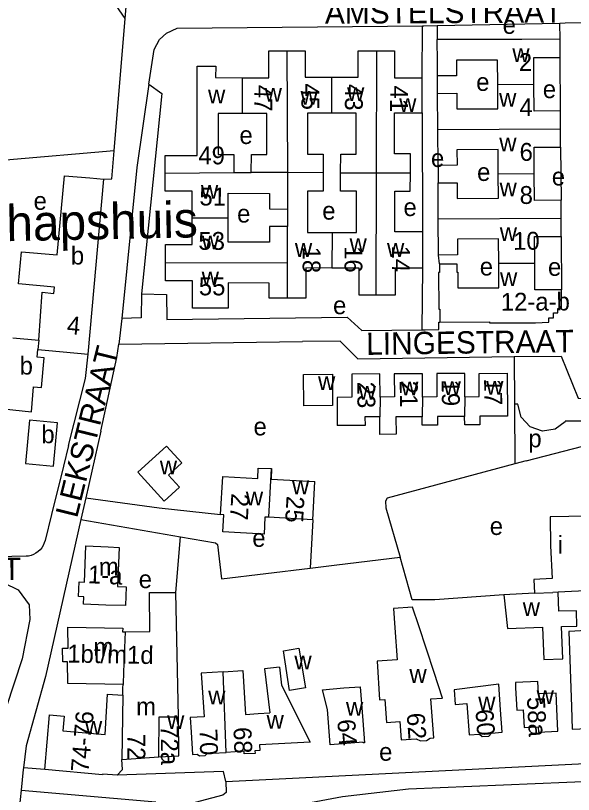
# Model space of a CAD drawing. Extents: x 156721 to 158827, y 386657 to 388950.
# Drawn here: x 157877.1 to 158001.9, y 387819.8 to 387994 of the extents above; entities that cross this region are included whole.
import ezdxf

# ---------------------------------------------------------------- set-up
doc = ezdxf.new("R2010")
doc.units = 0
for name, color, linetype in [('BLT_Basislijn', 7, 'Continuous'), ('BLT_Bebouwing', 7, 'Continuous'), ('BLT_Bebouwing_beschrifting', 7, 'Continuous'), ('BLT_Centroide', 7, 'Continuous'), ('BLT_Huisnummer', 7, 'Continuous'), ('BLT_Huisnummer_ tussenligend', 7, 'Continuous'), ('BLT_Huisnummer_reeks', 7, 'Continuous'), ('BLT_Onderverdeling_panden', 7, 'Continuous'), ('BLT_Straatnaam', 7, 'Continuous')]:
    doc.layers.add(name, color=color, linetype=linetype)

msp = doc.modelspace()

# ---------------------------------------------------------------- linework, layer by layer
at = {"layer": 'BLT_Basislijn'}
for p, q in [((157899.13, 387963.78), (157901.62, 387993.36)), ((157968.02, 387980.09), (157968.06, 387991.73)), ((157971.35, 387991.78), (157998.82, 387992.34)), ((157971.35, 387991.78), (157971.4, 387988.63)), ((157998.87, 387988.71), (157998.82, 387992.34)), ((157998.96, 387972.69), (157998.9, 387984.64)), ((157971.48, 387976.61), (157971.45, 387980.53)), ((157968, 387972.25), (157968.1, 387945.64)), ((157999, 387964.6), (157999.09, 387952.71)), ((157971.57, 387960.51), (157971.57, 387956.59)), ((157999.14, 387944.62), (157999.19, 387932.68)), ((157971.9, 387938.5), (157971.66, 387940.45)), ((157968.08, 387937.52), (157967.93, 387923.75)), ((157900.86, 387926.26), (157900.15, 387920.51)), ((157900.15, 387920.51), (157941.29, 387921.13)), ((157953.6, 387917.26), (157988.63, 387917.77)), ((157988.63, 387917.77), (157988.69, 387907.1)), ((157988.69, 387907.1), (157988.77, 387893.76)), ((158000.11, 387903.37), (158026.76, 387903.49)), ((157896.14, 387901.07), (157892.77, 387886.15)), ((157991.27, 387894.43), (158008.88, 387899.04)), ((157888.94, 387897.89), (157887.79, 387893.25)), ((157887.79, 387893.25), (157885.11, 387882.45)), ((157892.77, 387886.15), (157891.67, 387881.33)), ((157885.11, 387882.45), (157883.67, 387876.65)), ((157891.67, 387881.33), (157913.95, 387877.46)), ((157943.53, 387881.27), (157943, 387870.43)), ((157912.94, 387865.01), (157913.95, 387877.46)), ((157879.41, 387873.08), (157866.57, 387872.9)), ((157883.61, 387825.37), (157878.83, 387825.77)), ((157924.07, 387822.72), (158010.48, 387827.06)), ((157878.29, 387820.78), (157908.48, 387818.14))]:
    msp.add_line(p, q, dxfattribs=at)
for points in [[(157901.62, 387993.36), (157898.09, 387998.47), (157897.02, 388000.69), (157896.24, 388041.41), (157895.78, 388042.36), (157892.24, 388044.78)], [(157901.62, 387993.36), (157901.91, 387996.85), (157904.01, 387996.92)], [(157906.88, 387978.67), (157908.09, 387986.41), (157909.3, 387988.64), (157910.8, 387990.08), (157913.24, 387991.17), (157968.06, 387991.73)], [(157968.06, 387991.73), (157968.39, 387991.73), (157971.35, 387991.78)], [(157998.82, 387992.34), (157999.99, 387992.36), (158006.77, 387992.45)], [(157906.88, 387978.67), (157904.21, 387960.07), (157900.86, 387926.26)], [(157906.88, 387978.67), (157909.79, 387976.62), (157905.23, 387931.8)], [(157899.13, 387963.78), (157874.87, 387961.65)], [(157896.83, 387957.41), (157898.6, 387957.51), (157899.13, 387963.78)], [(157905.23, 387931.8), (157905.13, 387926.4), (157900.86, 387926.26)], [(157905.23, 387931.8), (157910.84, 387931.63), (157910.93, 387926.07), (157951.27, 387926.55), (157954.56, 387923.56), (157967.93, 387923.75)], [(157971.73, 387923.79), (157971.73, 387925.44), (157971.95, 387925.44)], [(157967.93, 387923.75), (157968.68, 387923.76), (157971.73, 387923.79)], [(157896.14, 387901.07), (157899.73, 387917.52), (157900.15, 387920.51)], [(157953.6, 387917.26), (157949.7, 387921.17), (157941.29, 387921.13)], [(157888.94, 387897.89), (157892.75, 387912.84), (157893.3, 387918.28)], [(157988.63, 387917.77), (157999.1, 387917.81), (158002.93, 387908.43), (158009.43, 387908.41)], [(158000.11, 387903.37), (158000, 387903.14), (157997.74, 387901.5), (157994.97, 387901.07), (157992.16, 387902.04), (157990.14, 387904.22), (157989.43, 387907.11), (157988.69, 387907.1)], [(157988.77, 387893.76), (157960.18, 387886.1), (157959.79, 387885.42)], [(157991.27, 387894.43), (157988.77, 387893.76)], [(157892.77, 387886.15), (157909.16, 387883.95), (157922.94, 387882.41)], [(157959.79, 387885.42), (157959.92, 387883.94), (157963.07, 387872.89)], [(157891.67, 387881.33), (157883.75, 387846.18), (157879.46, 387830.71), (157878.83, 387825.77)], [(157883.67, 387876.65), (157883.5, 387876.07), (157883.26, 387875.52), (157882.95, 387875), (157882.57, 387874.53), (157882.13, 387874.12), (157881.64, 387873.77), (157881.11, 387873.48), (157880.55, 387873.27), (157879.96, 387873.13), (157879.41, 387873.08)], [(157913.95, 387877.46), (157921.83, 387876.09), (157922.24, 387875.71), (157923.13, 387868.05), (157943, 387870.43)], [(157943, 387870.43), (157948.92, 387871.14), (157963.07, 387872.89)], [(157986.29, 387864.45), (157970.85, 387863.35), (157965.79, 387863.37), (157963.07, 387872.89)], [(157841.97, 387866.69), (157874.43, 387867.12), (157877.68, 387865.6), (157880.08, 387862.25), (157880.27, 387858.93), (157878.55, 387850.12), (157874.95, 387839.3), (157872.31, 387828.07)], [(157878.83, 387825.77), (157878.79, 387825.42), (157878.29, 387820.78)], [(157924.07, 387822.72), (157923.55, 387824.93), (157899.81, 387824.11)], [(157926.23, 387812.97), (157939.48, 387817.32), (157950.17, 387819.38), (157964.96, 387821.05), (158050, 387824.67)], [(157924.07, 387822.72), (157924.19, 387820.24), (157923.41, 387819.68), (157908.49, 387815.69)], [(157878.29, 387820.78), (157877.85, 387816.63), (157877.67, 387804.99)]]:
    msp.add_lwpolyline(points, dxfattribs=at)
at = {"layer": 'BLT_Bebouwing'}
for p, q in [((157998.9, 387984.64), (157998.87, 387988.71)), ((157971.52, 387968.56), (157971.48, 387976.61)), ((157998.98, 387968.71), (157998.96, 387972.69)), ((157971.57, 387960.51), (157971.52, 387968.56)), ((157999, 387964.6), (157998.98, 387968.71)), ((157925.92, 387958.95), (157929.8, 387958.94)), ((157893.3, 387918.28), (157896.83, 387957.41)), ((157971.62, 387948.52), (157971.57, 387956.59)), ((157999.11, 387948.67), (157999.09, 387952.71)), ((157937.9, 387950.75), (157937.9, 387946.86)), ((157971.66, 387940.45), (157971.62, 387948.52)), ((157884.48, 387919.08), (157893.3, 387918.28)), ((157941.47, 387913.73), (157947.97, 387913.79)), ((157941.52, 387906.74), (157941.47, 387913.73)), ((157880.17, 387903.5), (157879.27, 387893.84)), ((157910.85, 387897.71), (157904.43, 387891.88)), ((157914.25, 387893.96), (157910.85, 387897.71)), ((157879.27, 387893.84), (157885.54, 387893.26)), ((157911.27, 387891.26), (157914.25, 387893.96)), ((157910.28, 387885.43), (157904.43, 387891.88)), ((157934.33, 387892.69), (157934.21, 387890.36)), ((157911.27, 387891.26), (157913.74, 387888.57)), ((157910.28, 387885.43), (157913.74, 387888.57)), ((157943.53, 387881.27), (157944, 387889.82)), ((157913.55, 387837.21), (157912.94, 387865.01)), ((157993.12, 387864.81), (157986.29, 387864.45)), ((158009.5, 387865.58), (157998.46, 387865.05)), ((157998.56, 387860.82), (157998.46, 387865.05)), ((157936.08, 387848.31), (157936.58, 387844.29)), ((157936.58, 387844.29), (157942.96, 387831.51)), ((157931.33, 387837.89), (157933.98, 387838.04)), ((157900.83, 387827.63), (157909.15, 387828.2))]:
    msp.add_line(p, q, dxfattribs=at)
for points in [[(157998.87, 387988.71), (157990.34, 387988.67), (157971.4, 387988.63)], [(157971.45, 387980.53), (157971.43, 387983.63), (157971.4, 387988.63)], [(157927.77, 387980.12), (157933.71, 387980.1), (157933.72, 387986.16), (157937.77, 387986.15)], [(157937.77, 387986.15), (157941.83, 387986.14), (157941.82, 387980.26), (157947.77, 387980.25)], [(157947.77, 387980.25), (157953.73, 387980.24), (157953.74, 387986.12), (157957.79, 387986.11)], [(157957.79, 387986.11), (157961.84, 387986.11), (157961.82, 387980.11), (157968.02, 387980.09)], [(157993, 387978.66), (157992.97, 387984.61), (157998.9, 387984.64)], [(157910.52, 387958.74), (157910.53, 387962.71), (157917.67, 387962.69), (157917.72, 387982.68), (157921.84, 387982.67), (157921.83, 387980.13), (157927.77, 387980.12)], [(157984.94, 387978.62), (157984.91, 387984.06), (157975.7, 387984.01), (157975.72, 387980.55), (157971.45, 387980.53)], [(157968, 387972.25), (157968.01, 387975.1), (157968.02, 387980.09)], [(157971.48, 387976.61), (157975.75, 387976.64), (157975.77, 387973.13), (157984.97, 387973.18), (157984.94, 387978.62)], [(157998.96, 387972.69), (157993.04, 387972.66), (157993, 387978.66)], [(157927.75, 387972.13), (157922.4, 387972.14), (157922.38, 387962.93), (157925.93, 387962.92), (157925.92, 387958.95)], [(157929.8, 387958.94), (157929.81, 387962.95), (157933.28, 387962.95), (157933.3, 387972.12), (157927.75, 387972.13)], [(157947.75, 387972.2), (157942.38, 387972.21), (157942.36, 387963.02), (157945.89, 387963.01), (157945.88, 387958.87)], [(157949.79, 387958.88), (157949.8, 387963.04), (157953.27, 387963.04), (157953.29, 387972.19), (157947.75, 387972.2)], [(157965.38, 387958.85), (157965.39, 387963.07), (157961.85, 387963.08), (157961.87, 387972.27), (157968, 387972.25)], [(157985.04, 387958.61), (157985.01, 387964.05), (157975.81, 387964.01), (157975.83, 387960.53), (157971.57, 387960.51)], [(157993.08, 387958.66), (157993.05, 387964.56), (157999, 387964.6)], [(157885.63, 387931.88), (157885.78, 387933.31), (157877.75, 387934.03), (157878.4, 387941.21), (157886.4, 387940.48), (157888.01, 387958.2), (157893.65, 387957.69), (157896.83, 387957.41)], [(157916.6, 387948.79), (157916.61, 387954.76), (157910.51, 387954.77), (157910.52, 387958.74)], [(157945.88, 387958.87), (157945.87, 387954.72), (157942.41, 387954.73), (157942.39, 387945.53), (157947.87, 387945.52)], [(157947.87, 387945.52), (157953.34, 387945.5), (157953.36, 387954.72), (157949.78, 387954.73), (157949.79, 387958.88)], [(157968.1, 387945.64), (157961.91, 387945.65), (157961.93, 387954.77), (157965.37, 387954.77), (157965.38, 387958.85)], [(157971.57, 387956.59), (157975.85, 387956.62), (157975.87, 387953.13), (157985.07, 387953.18), (157985.04, 387958.61)], [(157999.09, 387952.71), (157993.12, 387952.68), (157993.08, 387958.66)], [(157924.65, 387948.77), (157924.66, 387954.26), (157933.87, 387954.24), (157933.86, 387950.76), (157937.9, 387950.75)], [(157910.61, 387938.76), (157910.62, 387942.83), (157916.59, 387942.82), (157916.6, 387948.79)], [(157937.9, 387946.86), (157933.91, 387946.87), (157933.9, 387943.35), (157924.63, 387943.37), (157924.65, 387948.77)], [(157999.14, 387944.62), (157999.11, 387948.67)], [(157968.1, 387945.64), (157968.09, 387942.52), (157968.08, 387937.52)], [(157993.21, 387938.65), (157993.18, 387944.59), (157999.14, 387944.62)], [(157985.15, 387938.61), (157985.12, 387944.06), (157975.94, 387944.01), (157975.95, 387940.47), (157971.66, 387940.45)], [(157937.9, 387930.79), (157933.82, 387930.8), (157933.82, 387934.2), (157924.64, 387934.22), (157924.63, 387928.58), (157916.67, 387928.6), (157916.68, 387934.67), (157910.6, 387934.68), (157910.61, 387938.76)], [(157947.85, 387937.56), (157941.99, 387937.57), (157941.98, 387930.78), (157937.9, 387930.79)], [(157957.67, 387931.52), (157953.9, 387931.52), (157953.92, 387937.54), (157947.85, 387937.56)], [(157968.08, 387937.52), (157962, 387937.53), (157961.99, 387931.51), (157957.67, 387931.52)], [(157971.9, 387938.5), (157971.92, 387936.55), (157971.68, 387936.55), (157971.72, 387928.34), (157971.94, 387928.34), (157971.95, 387925.44)], [(157971.9, 387938.5), (157975.75, 387938.52), (157975.76, 387936.65), (157976, 387936.65), (157976.02, 387933.11), (157985.17, 387933.16), (157985.15, 387938.61)], [(157999.19, 387932.68), (157993.24, 387932.65), (157993.21, 387938.65)], [(157882.26, 387921.42), (157883.05, 387932.13), (157885.63, 387931.88)], [(157999.21, 387928.49), (157999.19, 387932.68)], [(157971.95, 387925.44), (157983.11, 387925.5), (157983.11, 387925.28), (157993.34, 387925.33), (157996.34, 387925.44), (157996.33, 387926.45), (157997.4, 387926.45), (157997.39, 387927.5), (157998.35, 387927.51), (157998.34, 387928.47), (157999.21, 387928.49)], [(157876.48, 387921.94), (157882.26, 387921.42)], [(157874.37, 387906.03), (157880.62, 387905.36), (157881.12, 387910.97), (157882.88, 387910.81), (157883.48, 387917.47), (157881.88, 387917.61), (157882.03, 387919.3)], [(157882.03, 387919.3), (157884.48, 387919.08)], [(157947.97, 387913.79), (157948, 387906.78), (157941.52, 387906.74)], [(157958.64, 387908.68), (157958.58, 387913.86), (157952.27, 387913.81), (157952.3, 387908.64), (157948.99, 387908.59), (157949.02, 387902.32)], [(157968.08, 387908.71), (157968.06, 387913.92), (157961.78, 387913.9), (157961.84, 387908.72), (157958.64, 387908.68)], [(157977.6, 387908.77), (157977.57, 387913.96), (157971.27, 387913.94), (157971.29, 387908.72), (157968.08, 387908.71)], [(157977.6, 387908.77), (157980.81, 387908.79), (157980.77, 387913.98), (157987.05, 387914.01), (157987.14, 387904.43), (157980.92, 387904.4), (157980.92, 387902.49), (157977.53, 387902.46), (157977.52, 387904.36)], [(157958.55, 387904.28), (157955.23, 387904.27), (157955.24, 387902.35), (157949.02, 387902.32)], [(157968.04, 387904.29), (157962.15, 387904.25), (157962.18, 387900.39), (157958.56, 387900.35), (157958.55, 387904.28)], [(157977.52, 387904.36), (157971.45, 387904.35), (157971.46, 387902.43), (157968.05, 387902.41), (157968.04, 387904.29)], [(157885.54, 387893.26), (157886.43, 387902.91), (157880.17, 387903.5)], [(157922.94, 387882.41), (157923.41, 387890.93), (157931.24, 387890.5), (157931.37, 387892.82), (157934.21, 387892.7)], [(157934.21, 387892.7), (157934.33, 387892.69)], [(157934.21, 387890.36), (157944, 387889.82)], [(157933.68, 387881.81), (157932.86, 387881.86), (157932.65, 387878.02), (157923.44, 387878.53), (157923.66, 387882.37), (157922.94, 387882.41)], [(157943.53, 387881.27), (157933.68, 387881.81)], [(158009.16, 387882.14), (157996.64, 387881.91), (157996.76, 387875.44), (157997.09, 387868.09)], [(157897.81, 387875.18), (157900.27, 387875.08), (157899.89, 387866.34), (157901.82, 387866.29), (157901.66, 387862.05), (157897.26, 387862.17), (157892.26, 387862.39), (157892.33, 387864.03), (157891.15, 387864.08), (157891.29, 387867.34), (157892.46, 387867.29), (157892.81, 387875.4), (157897.81, 387875.18)], [(157997.09, 387868.09), (157992.97, 387867.93), (157993.12, 387864.81)], [(157901.6, 387856.2), (157907.09, 387856.23), (157907.04, 387864.98), (157912.94, 387865.01)], [(157986.29, 387864.45), (157987.12, 387856.97), (157994.95, 387857.26), (157995.26, 387849.98), (157999.48, 387850.16), (157999.17, 387857.36), (158002.6, 387857.44), (158002.52, 387860.92), (157998.56, 387860.82)], [(157967.26, 387857.51), (157965.88, 387861.7), (157961.6, 387861.39), (157961.93, 387857.12), (157962.41, 387849.92), (157957.97, 387849.65), (157958.49, 387841), (157959.65, 387841.09), (157960.02, 387835.94), (157963.03, 387836.16), (157963.33, 387832.04), (157966.66, 387832.28), (157967.65, 387831.8), (157969.01, 387831.9), (157969.8, 387832.43), (157970.65, 387832.5), (157969.96, 387841.19), (157972.58, 387841.36), (157970.7, 387847.08), (157967.26, 387857.51)], [(157901.14, 387844.43), (157888.73, 387844.66), (157888.71, 387849.47), (157887.62, 387849.47), (157887.6, 387852.56), (157888.81, 387852.56), (157888.79, 387857.26), (157901.03, 387856.98), (157901.01, 387856.19), (157901.6, 387856.2)], [(158010.06, 387847.03), (158005.34, 387846.76), (158004.78, 387856.47), (158000.8, 387856.28)], [(158000.8, 387856.28), (158001.39, 387839.39), (158001.56, 387834.39), (158006.8, 387834.63), (158006.59, 387838.37), (158010.12, 387838.57)], [(157936.99, 387851.94), (157940.44, 387852.51), (157941.9, 387843.66), (157938.38, 387843.05), (157936.99, 387851.94)], [(157923.48, 387847.25), (157918.59, 387846.96), (157919.24, 387837.19), (157916.15, 387837.03), (157916.34, 387833.76), (157916.63, 387828.77), (157917.68, 387828.83), (157918.2, 387828.43), (157919.51, 387828.51), (157919.91, 387828.96), (157921.16, 387829.03), (157924.16, 387829.23)], [(157923.48, 387847.25), (157927.93, 387847.51), (157928.5, 387837.73), (157931.33, 387837.89)], [(157936.08, 387848.31), (157932.77, 387847.9), (157933.98, 387838.04)], [(157998.14, 387838.94), (157997.96, 387842.49), (157994.03, 387842.3), (157993.89, 387845.09), (157988.87, 387844.85), (157988.92, 387843.7), (157989.17, 387838.7), (157990.64, 387838.78), (157990.83, 387834.83), (157993.99, 387834.98), (157994.05, 387833.73), (157998.38, 387833.94), (157998.14, 387838.94)], [(157901.05, 387842.05), (157901.07, 387843.66), (157901.14, 387844.43)], [(157954.73, 387836.36), (157955.13, 387831.38), (157954.81, 387831.35), (157954.8, 387831.49), (157947.47, 387830.9), (157947.07, 387835.89), (157946.83, 387838.8), (157945.72, 387843.24), (157950.52, 387843.63), (157954.12, 387843.92), (157954.73, 387836.36)], [(157985.58, 387838.72), (157985.18, 387844.48), (157975.19, 387843.23), (157975.42, 387839.94), (157978.02, 387840.13), (157978.51, 387833.15), (157980.85, 387833.31), (157981.48, 387832.77), (157982.92, 387832.87), (157983.52, 387833.56), (157985.94, 387833.73), (157985.58, 387838.72)], [(157883.61, 387825.37), (157884.68, 387837.64), (157887.94, 387837.36), (157887.65, 387834.07), (157897.14, 387833.24), (157897.65, 387842.24), (157901.05, 387842.05)], [(157909.15, 387828.2), (157913.59, 387828.49), (157913.55, 387837.21)], [(157931.62, 387830.95), (157931.7, 387829.64), (157930.6, 387829.58), (157930.64, 387829.01), (157928.24, 387828.87), (157928.2, 387829.5), (157924.16, 387829.23)], [(157942.96, 387831.51), (157931.62, 387830.95)], [(157899.81, 387824.11), (157900.98, 387825.39), (157900.83, 387827.63)], [(157899.81, 387824.11), (157896.56, 387824.39), (157896.53, 387824.21), (157883.61, 387825.37)]]:
    msp.add_lwpolyline(points, dxfattribs=at)
at = {"layer": 'BLT_Onderverdeling_panden'}
for p, q in [((157937.77, 387986.15), (157937.88, 387958.9)), ((157957.79, 387986.11), (157957.73, 387958.87)), ((157927.77, 387980.12), (157927.75, 387972.13)), ((157947.77, 387980.25), (157947.75, 387972.2)), ((157984.94, 387978.62), (157993, 387978.66)), ((157971.52, 387968.56), (157998.98, 387968.71)), ((157910.52, 387958.74), (157925.92, 387958.95)), ((157937.88, 387958.9), (157929.8, 387958.94)), ((157937.88, 387958.9), (157937.9, 387950.75)), ((157945.88, 387958.87), (157937.88, 387958.9)), ((157949.79, 387958.88), (157957.73, 387958.87)), ((157957.73, 387958.87), (157957.67, 387931.52)), ((157957.73, 387958.87), (157965.38, 387958.85)), ((157985.04, 387958.61), (157993.08, 387958.66)), ((157916.6, 387948.79), (157924.65, 387948.77)), ((157971.62, 387948.52), (157999.11, 387948.67)), ((157937.9, 387938.7), (157937.9, 387946.86)), ((157947.87, 387945.52), (157947.85, 387937.56)), ((157910.61, 387938.76), (157937.9, 387938.7)), ((157937.9, 387930.79), (157937.9, 387938.7)), ((157985.15, 387938.61), (157993.21, 387938.65)), ((157882.26, 387921.42), (157882.03, 387919.3)), ((157958.64, 387908.68), (157958.55, 387904.28)), ((157968.08, 387908.71), (157968.04, 387904.29)), ((157977.6, 387908.77), (157977.52, 387904.36)), ((157934.21, 387892.7), (157933.68, 387881.81)), ((157993.12, 387864.81), (157997.22, 387865)), ((157998.46, 387865.05), (157997.22, 387865)), ((157901.6, 387856.2), (157901.25, 387847.21)), ((157924.16, 387829.23), (157923.48, 387847.25))]:
    msp.add_line(p, q, dxfattribs=at)
for points in [[(157901.25, 387847.21), (157901.14, 387844.43)], [(157901.05, 387842.05), (157900.83, 387827.63)], [(157909.15, 387828.2), (157909.16, 387837.21), (157913.55, 387837.21)]]:
    msp.add_lwpolyline(points, dxfattribs=at)

# ---------------------------------------------------------------- texts
at = {"layer": 'BLT_Bebouwing_beschrifting'}
msp.add_text('Gemeenschapshuis', height=8, rotation=1.1997, dxfattribs=at).set_placement((157823.37, 387942.46))
at = {"layer": 'BLT_Centroide'}
for s, p in [('e', (157986.02, 387989.94)), ('w', (157988.19, 387983.64)), ('e', (157980.11, 387977.17)), ('w', (157920.12, 387974.37)), ('w', (157932.79, 387974.76)), ('w', (157951.23, 387974.92)), ('e', (157995.01, 387975.56)), ('w', (157940.81, 387974.06)), ('w', (157962.88, 387972.47)), ('w', (157985.23, 387973.62)), ('e', (157927.15, 387965.29)), ('w', (157985.27, 387963.62)), ('e', (157969.99, 387960.15)), ('e', (157980.31, 387957.03)), ('e', (157997.02, 387956.03)), ('w', (157985.34, 387953.61)), ('w', (157918.54, 387953.05)), ('e', (157881.1, 387950.58)), ('e', (157945.67, 387948.38)), ('e', (157963.84, 387949.18)), ('e', (157926.63, 387947.73)), ('w', (157985.38, 387943.61)), ('w', (157918.71, 387941.7)), ('w', (157951.78, 387941.15)), ('b', (157889.44, 387938.34)), ('w', (157939.56, 387940.05)), ('w', (157960.16, 387940.05)), ('e', (157980.91, 387935.89)), ('e', (157996.17, 387935.81)), ('w', (157918.71, 387933.66)), ('w', (157985.44, 387933.52)), ('e', (157948.09, 387927.23)), ('b', (157877.98, 387913.73)), ('w', (157944.73, 387910.25)), ('w', (157953.81, 387908.08)), ('w', (157963.31, 387909.08)), ('w', (157972.81, 387909.14)), ('w', (157982.33, 387909.2)), ('b', (157882.84, 387898.38)), ('e', (157930.3, 387900.12)), ('p', (157991.78, 387897.46)), ('w', (157909.34, 387891.41)), ('w', (157938.89, 387886.97)), ('w', (157928.58, 387884.45)), ('e', (157983.14, 387877.85)), ('e', (157930.02, 387875.21)), ('i', (157998.36, 387873.66)), ('m', (157895.7, 387868.77)), ('e', (157904.62, 387865.97)), ('w', (157990.52, 387859.74)), ('m', (157894.5, 387850.84)), ('w', (157939.44, 387847.78)), ('w', (157965.17, 387844.77)), ('w', (157993.62, 387840.03)), ('w', (157920.16, 387839.97)), ('w', (157980.56, 387838.59)), ('m', (157904.03, 387837.5)), ('w', (157950.98, 387837.42)), ('w', (157892.59, 387833.16)), ('w', (157910.97, 387834.48)), ('w', (157933.22, 387834.52)), ('e', (157958.39, 387827.36))]:
    msp.add_text(s, height=4, dxfattribs=at).set_placement(p)
at = {"layer": 'BLT_Huisnummer'}
for s, rotation, p in [('2', 0.3054, (157989.65, 387981.6)), ('47', 269.8781, (157930.52, 387978.52)), ('41', 269.8738, (157960.87, 387978.38)), ('6', 0.3054, (157989.82, 387961.52)), ('49', 359.8869, (157917.95, 387960.75)), ('18', 270.007, (157941.29, 387942.36)), ('14', 269.8722, (157961.27, 387942.58)), ('55', 359.8777, (157918.06, 387931.45)), ('4', 354.846, (157888.44, 387922.86)), ('23', 270.3327, (157953.51, 387912.13)), ('17', 270.4973, (157981.88, 387912.81)), ('27', 266.8246, (157925.36, 387887.22)), ('25', 266.8246, (157937.71, 387886.65)), ('58a', 272.8081, (157991.46, 387841.57)), ('62', 274.1282, (157964.56, 387837.94)), ('60', 274.0477, (157979.94, 387838.75)), ('64', 274.625, (157949.02, 387836.5)), ('72a', 270.2953, (157909.55, 387835.31)), ('68', 272.4286, (157925.8, 387834.81)), ('72', 269.7669, (157902.11, 387833.41)), ('70', 271.5785, (157918.21, 387834.47))]:
    msp.add_text(s, height=4, rotation=rotation, dxfattribs=at).set_placement(p)
at = {"layer": 'BLT_Huisnummer_ tussenligend'}
for s, rotation, p in [('45', 270.2145, (157940.99, 387978.86)), ('43', 269.879, (157950.75, 387978.72)), ('4', 0.3054, (157989.8, 387971.53)), ('51', 359.8756, (157918.19, 387951.54)), ('8', 0.3054, (157989.83, 387951.88)), ('53', 359.8826, (157917.96, 387941.62)), ('10', 0.3054, (157988.37, 387941.62)), ('16', 269.8776, (157950.66, 387942.47)), ('21', 270.4973, (157963.01, 387912.34)), ('19', 270.4973, (157972.4, 387912.59))]:
    msp.add_text(s, height=4, rotation=rotation, dxfattribs=at).set_placement(p)
at = {"layer": 'BLT_Huisnummer_reeks'}
for s, rotation, p in [('12-a-b', 0.3054, (157985.61, 387927.99)), ('1-a', 357.5358, (157893.19, 387867.07)), ('1bt/m1d', 358.9598, (157888.6, 387849.33)), ('74-76', 85.0162, (157893.4, 387824.68))]:
    msp.add_text(s, height=4, rotation=rotation, dxfattribs=at).set_placement(p)
at = {"layer": 'BLT_Straatnaam'}
for s, rotation, p in [('AMSTELSTRAAT', 0.2861, (157946.27, 387992.18)), ('LINGESTRAAT', 0.7713, (157955.53, 387918.12)), ('LEKSTRAAT', 76.1162, (157890.82, 387881.45)), ('IJSSELSTRAAT', 0.7788, (157829.66, 387867.15))]:
    msp.add_text(s, height=5, rotation=rotation, dxfattribs=at).set_placement(p)

doc.saveas('drawing.dxf')
